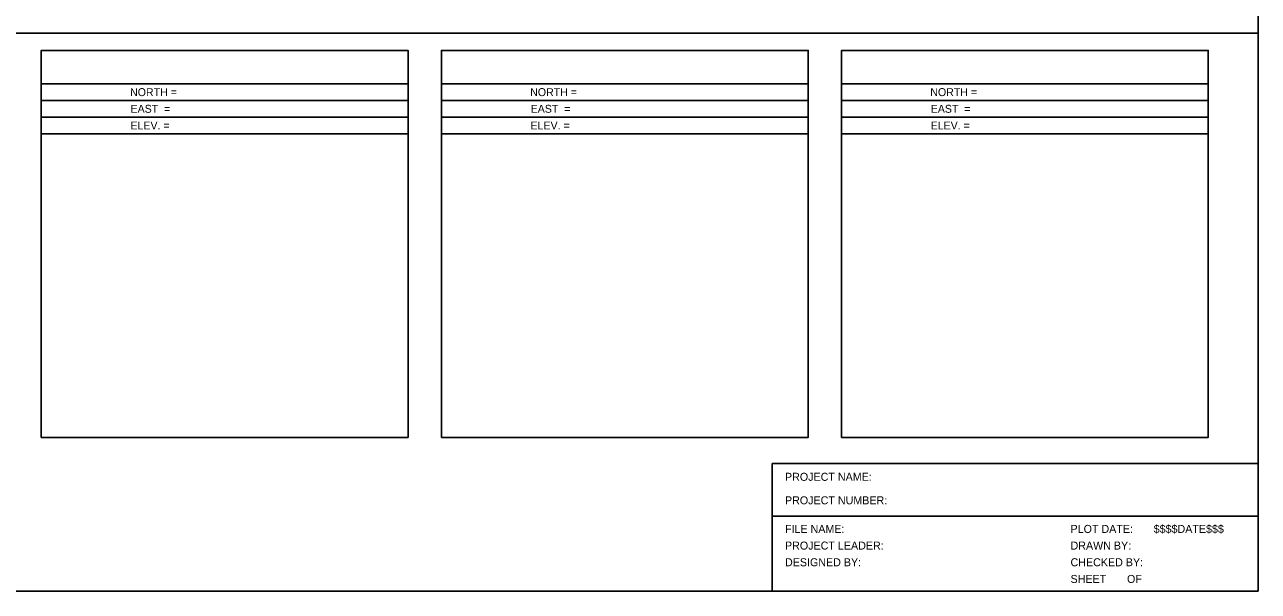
# Model space of a CAD drawing. Extents: x 1613599 to 1614239, y 299188 to 300574.
# Drawn here: x 1613868.5 to 1614238.5, y 299187.8 to 299357.7 of the extents above; entities that cross this region are included whole.
import ezdxf

# ---------------------------------------------------------------- set-up
doc = ezdxf.new("R2010")
doc.units = 0
doc.layers.add('NBL1', color=7, linetype='Continuous')

msp = doc.modelspace()

# ---------------------------------------------------------------- linework, layer by layer
at = {"layer": 'NBL1'}
for p, q in [((1613598.53, 299355.13), (1614238.53, 299355.13)), ((1613983.53, 299339.96), (1613873.53, 299339.96)), ((1614103.53, 299339.96), (1613993.53, 299339.96)), ((1614223.53, 299339.96), (1614113.53, 299339.96)), ((1613983.53, 299334.96), (1613873.53, 299334.96)), ((1614103.53, 299334.96), (1613993.53, 299334.96)), ((1614223.53, 299334.96), (1614113.53, 299334.96)), ((1613983.53, 299329.96), (1613873.53, 299329.96)), ((1614103.53, 299329.96), (1613993.53, 299329.96)), ((1614223.53, 299329.96), (1614113.53, 299329.96)), ((1613983.53, 299324.96), (1613873.53, 299324.96)), ((1614103.53, 299324.96), (1613993.53, 299324.96)), ((1614223.53, 299324.96), (1614113.53, 299324.96)), ((1614092.7, 299226.13), (1614238.53, 299226.13)), ((1614092.7, 299187.8), (1614092.7, 299226.13)), ((1614092.7, 299210.3), (1614238.53, 299210.3))]:
    msp.add_line(p, q, dxfattribs=at)
for points in [[(1614238.53, 299187.8), (1613598.53, 299187.8), (1613598.53, 299607.8), (1614238.53, 299607.8)], [(1613873.53, 299233.96), (1613983.53, 299233.96), (1613983.53, 299349.96), (1613873.53, 299349.96)], [(1613993.53, 299233.96), (1614103.53, 299233.96), (1614103.53, 299349.96), (1613993.53, 299349.96)], [(1614113.53, 299233.96), (1614223.53, 299233.96), (1614223.53, 299349.96), (1614113.53, 299349.96)]]:
    msp.add_lwpolyline(points, close=True, dxfattribs=at)

# ---------------------------------------------------------------- texts
for s, height, p in [('NORTH =             ', 2.375, (1613900.15, 299336.28)), ('NORTH =             ', 2.375, (1614020.15, 299336.28)), ('NORTH =             ', 2.375, (1614140.15, 299336.28)), ('EAST  =             ', 2.375, (1613900.29, 299331.28)), ('EAST  =             ', 2.375, (1614020.29, 299331.28)), ('EAST  =             ', 2.375, (1614140.29, 299331.28)), ('ELEV. =             ', 2.375, (1613900.26, 299326.28)), ('ELEV. =             ', 2.375, (1614020.26, 299326.28)), ('ELEV. =             ', 2.375, (1614140.26, 299326.28)), ('PROJECT NAME:', 2.4, (1614096.57, 299220.93)), ('PROJECT NUMBER:', 2.4, (1614096.57, 299213.88)), ('FILE NAME:', 2.4, (1614096.57, 299205.31)), ('PLOT DATE:', 2.4, (1614182.21, 299205.31)), ('$$$$DATE$$$', 2.4, (1614207.15, 299205.31)), ('PROJECT LEADER:', 2.4, (1614096.57, 299200.31)), ('DRAWN BY:', 2.4, (1614182.21, 299200.31)), ('DESIGNED BY:', 2.4, (1614096.57, 299195.31)), ('CHECKED BY:', 2.4, (1614182.21, 299195.31)), ('SHEET       OF', 2.4, (1614182.21, 299190.31))]:
    msp.add_text(s, height=height, dxfattribs=at).set_placement(p)

doc.saveas('drawing.dxf')
